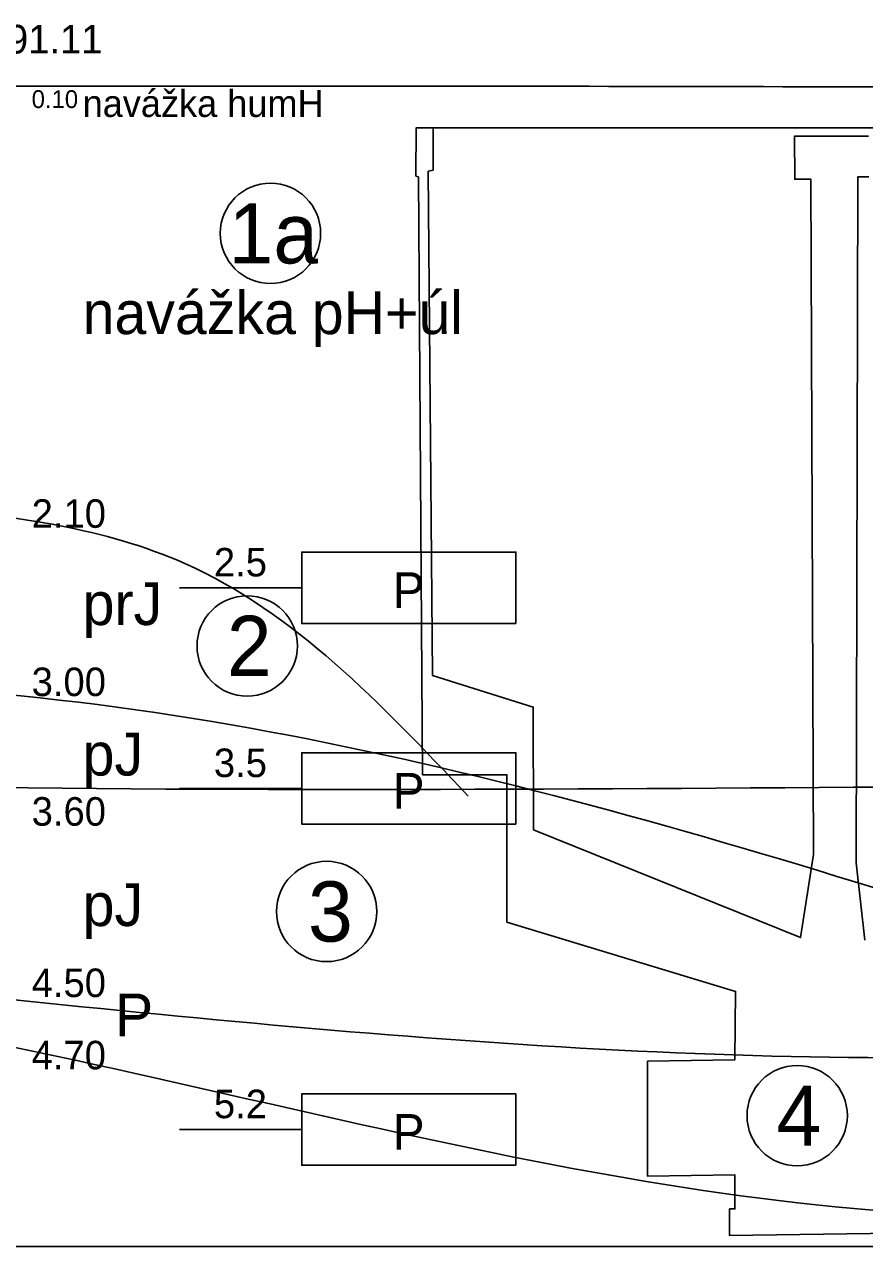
# Model space of a CAD drawing. Extents: x 3042 to 4120, y 576 to 2694.
# Drawn here: x 3337.94 to 3358.87, y 1987.57 to 2018.02 of the extents above; entities that cross this region are included whole.
import ezdxf

# ---------------------------------------------------------------- set-up
doc = ezdxf.new("R2010")
doc.units = 0
for name, color, linetype in [('17', 7, 'Continuous'), ('52', 7, 'Continuous'), ('62', 7, 'Continuous'), ('HPV', 7, 'Continuous'), ('komunikace', 7, 'Continuous'), ('nádrže', 7, 'Continuous'), ('rozhraní', 7, 'Continuous')]:
    doc.layers.add(name, color=color, linetype=linetype)

msp = doc.modelspace()

# ---------------------------------------------------------------- linework, layer by layer
at = {"layer": '62'}
for p, q in [((3341.804, 2003.985), (3344.852, 2003.985)), ((3341.804, 1998.985), (3344.852, 1998.985)), ((3341.804, 1990.485), (3344.852, 1990.485))]:
    msp.add_line(p, q, dxfattribs=at)
for points in [[(3350.186, 2003.096), (3344.852, 2003.096), (3344.852, 2004.874), (3350.186, 2004.874), (3350.186, 2003.096)], [(3350.186, 1998.096), (3344.852, 1998.096), (3344.852, 1999.874), (3350.186, 1999.874), (3350.186, 1998.096)], [(3350.186, 1989.596), (3344.852, 1989.596), (3344.852, 1991.374), (3350.186, 1991.374), (3350.186, 1989.596)]]:
    msp.add_lwpolyline(points, dxfattribs=at)
at = {"layer": 'HPV'}
msp.add_spline([(3240.524, 2002.483), (3248.732, 2002.483), (3335.452, 1999.034), (3390.312, 1998.782), (3416.672, 1997.683), (3427.31, 1997.599)], degree=3, dxfattribs=at)
at = {"layer": 'komunikace'}
msp.add_line((3430.025, 1987.57), (3299.437, 1987.57), dxfattribs=at)
at = {"layer": 'nádrže'}
msp.add_line((3347.703, 2015.45), (3368.323, 2015.45), dxfattribs=at)
for points in [[(3358.974, 2015.243), (3357.13, 2015.243), (3357.133, 2014.168), (3357.538, 2014.168), (3357.597, 1997.338), (3357.279, 1995.269), (3350.627, 1997.955), (3350.617, 2001.013), (3348.106, 2001.804), (3348.004, 2014.368), (3348.128, 2014.394), (3348.123, 2015.45), (3347.703, 2015.45), (3347.693, 2014.244), (3347.758, 2014.23)], [(3347.758, 2014.23), (3347.863, 1999.328), (3349.963, 1999.328), (3349.963, 1995.656), (3355.659, 1993.929), (3355.639, 1992.22), (3353.463, 1992.187), (3353.465, 1989.324), (3355.641, 1989.357), (3355.641, 1988.509), (3355.509, 1988.507), (3355.509, 1987.844), (3359.603, 1987.907)], [(3358.881, 1995.202), (3358.663, 1997.131), (3358.707, 2014.229), (3358.978, 2014.229)]]:
    msp.add_lwpolyline(points, dxfattribs=at)
at = {"layer": 'rozhraní'}
for centre in [(3344.071, 2012.819), (3343.491, 2002.538), (3343.491, 2002.538), (3345.469, 1995.92), (3357.194, 1990.832)]:
    msp.add_circle(centre, 1.25, dxfattribs=at)
for points in [[(3429.536, 2016.622), (3416.672, 2016.183), (3390.375, 2016.183), (3366.013, 2016.433), (3335.107, 2016.483), (3314.994, 2016.483)], [(3348.998, 1998.794), (3341.938, 2004.591), (3335.452, 2005.983), (3314.269, 2005.983)], [(3248.732, 2002.483), (3335.073, 1993.985), (3365.632, 1992.433), (3383.371, 1993.768), (3390.312, 1993.683)], [(3365.635, 1994.436), (3335.454, 2001.485), (3324.159, 2001.485)], [(3240.289, 1991.983), (3248.732, 1991.983), (3335.452, 1992.983), (3365.632, 1988.433), (3390.312, 1993.683), (3416.672, 1993.64), (3427.306, 1993.683)]]:
    msp.add_spline(points, degree=3, dxfattribs=at)

# ---------------------------------------------------------------- texts
at = {"layer": '17'}
for p in [(3336.976, 2017.301), (3336.978, 2017.303)]:
    msp.add_text('191.11', height=0.7112, dxfattribs=at).set_placement(p)
at = {"layer": '52'}
for s, height, p in [('0.10', 0.4445, (3338.121, 2015.941)), ('navážka humH', 0.6731, (3339.391, 2015.719)), ('navážka pH+úl', 1.0668, (3339.391, 2010.307)), ('2.10', 0.7112, (3338.121, 2005.481)), ('prJ', 1.0668, (3339.391, 2003.057)), ('3.00', 0.7112, (3338.121, 2001.287)), ('pJ', 1.0668, (3339.391, 1999.307)), ('3.60', 0.7112, (3338.121, 1998.058)), ('pJ', 1.0668, (3339.391, 1995.557)), ('4.50', 0.7112, (3338.121, 1993.787)), ('P', 1.067, (3340.198, 1992.807)), ('4.70', 0.7112, (3338.121, 1991.986))]:
    msp.add_text(s, height=height, dxfattribs=at).set_placement(p)
at = {"layer": '62'}
for s, height, p in [('2.5', 0.7112, (3342.661, 2004.269)), ('P', 0.889, (3347.117, 2003.483)), ('3.5', 0.7112, (3342.661, 1999.269)), ('P', 0.889, (3347.117, 1998.483)), ('5.2', 0.7112, (3342.661, 1990.769)), ('P', 0.889, (3347.117, 1989.983))]:
    msp.add_text(s, height=height, dxfattribs=at).set_placement(p)
at = {"layer": 'rozhraní'}
for s, p in [('1a', (3343.027, 2012.069)), ('2', (3342.983, 2001.788)), ('3', (3345.007, 1995.17)), ('4', (3356.678, 1990.082))]:
    msp.add_text(s, height=1.5, dxfattribs=at).set_placement(p)

doc.saveas('drawing.dxf')
